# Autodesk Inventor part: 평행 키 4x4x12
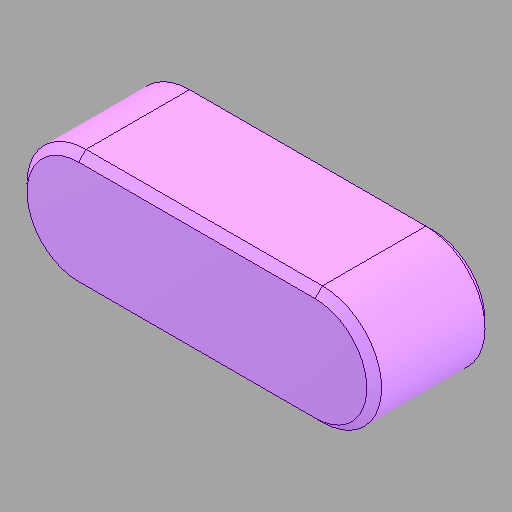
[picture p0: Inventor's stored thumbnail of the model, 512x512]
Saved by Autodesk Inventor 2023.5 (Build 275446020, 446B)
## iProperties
Created: 2026-03
Part Number: 평행 키 4x4x12
Material: 강철, 연강
Description: 키 및 해당 키홈
Document SubType Name: Modeling
Designer: mirae
Density: 7.85 g/cm^3
Appearance: 기본값
Author: jhkim
Sending System: Autodesk Inventor 2026
Preprocessor: ST-DEVELOPER v20.1
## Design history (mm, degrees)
node "평행 키 4x4x121"
node "솔리드1"
body "Solid1"
